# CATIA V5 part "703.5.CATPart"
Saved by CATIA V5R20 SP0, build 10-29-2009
Part number: 703.5
Revision: QUALSIASI
Definition: SCONOSCIUTO
Nomenclature: 703.5
Source: Unknown
Bounding box of the stored display mesh (mm): x -60 to 60, y -60 to 60, z 0 to 25
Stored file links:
  C:\Users\Utente\Desktop\IO LAVORO\3D X SITO CF\X 3D SITO CF 27-09-2020\703\703.5.CATPart
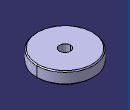
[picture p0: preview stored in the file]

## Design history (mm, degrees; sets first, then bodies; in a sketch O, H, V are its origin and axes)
Body1 "NONE" (main body)
  Solid1: solid without history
